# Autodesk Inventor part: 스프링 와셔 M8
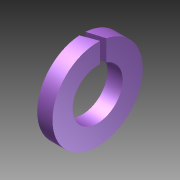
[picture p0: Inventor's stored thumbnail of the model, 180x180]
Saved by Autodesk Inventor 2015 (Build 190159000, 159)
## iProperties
Created: 2024-12
Part Number: 스프링 와셔 M8
Material: 일반
Document SubType Name: Modeling
Designer: 102566
Density: 1 g/cm^3
Appearance: 기본값
Author: 102566
Author: jhkim
Description: 스프링 잠금 와셔
Creation Date: 2024-11-28
Sending System: Autodesk Inventor 2025
Preprocessor: ST-DEVELOPER v20
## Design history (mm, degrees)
node "스프링 와셔 M81"
body "Solid1"
node "기준1"
